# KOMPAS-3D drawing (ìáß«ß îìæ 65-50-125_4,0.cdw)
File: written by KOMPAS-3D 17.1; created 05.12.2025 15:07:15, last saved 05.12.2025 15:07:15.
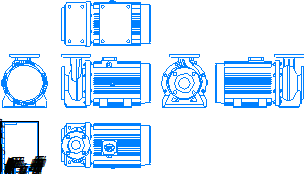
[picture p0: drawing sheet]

Sheet 1: A4, portrait

Title block, sheet 1: name: Насос МНС / 65-50-125_4,0; material: Сталь 10  ГОСТ 1050-88; mass: 130,87; sheets: 1; sheet format: A4

Views: Проекционный вид 2, Проекционный вид 3, Проекционный вид 4, Проекционный вид 5, Проекционный вид 6
Referenced files in \\adlc.lan\data\АДЛ_ПКД\3D-модели\ADL production\Насосы ГРАНПАМП\Насосы ГРАНПАМП серии МНС\KOMPAS 3D\: Насос МНС 65-50-125_4,0.m3d
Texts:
  Andrey
  АДЛ
Dimensions and other numbers on the sheet: 1:1; 1; 65-50-125_4,0; 130,87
